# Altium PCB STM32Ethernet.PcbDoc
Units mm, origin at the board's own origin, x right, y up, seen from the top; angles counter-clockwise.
Board outline 35 x 65 mm, 2 copper layers (Top Layer, Bottom Layer), stack 1.646 mm thick; 61 components, 67 nets, 261 pads, 74 vias.
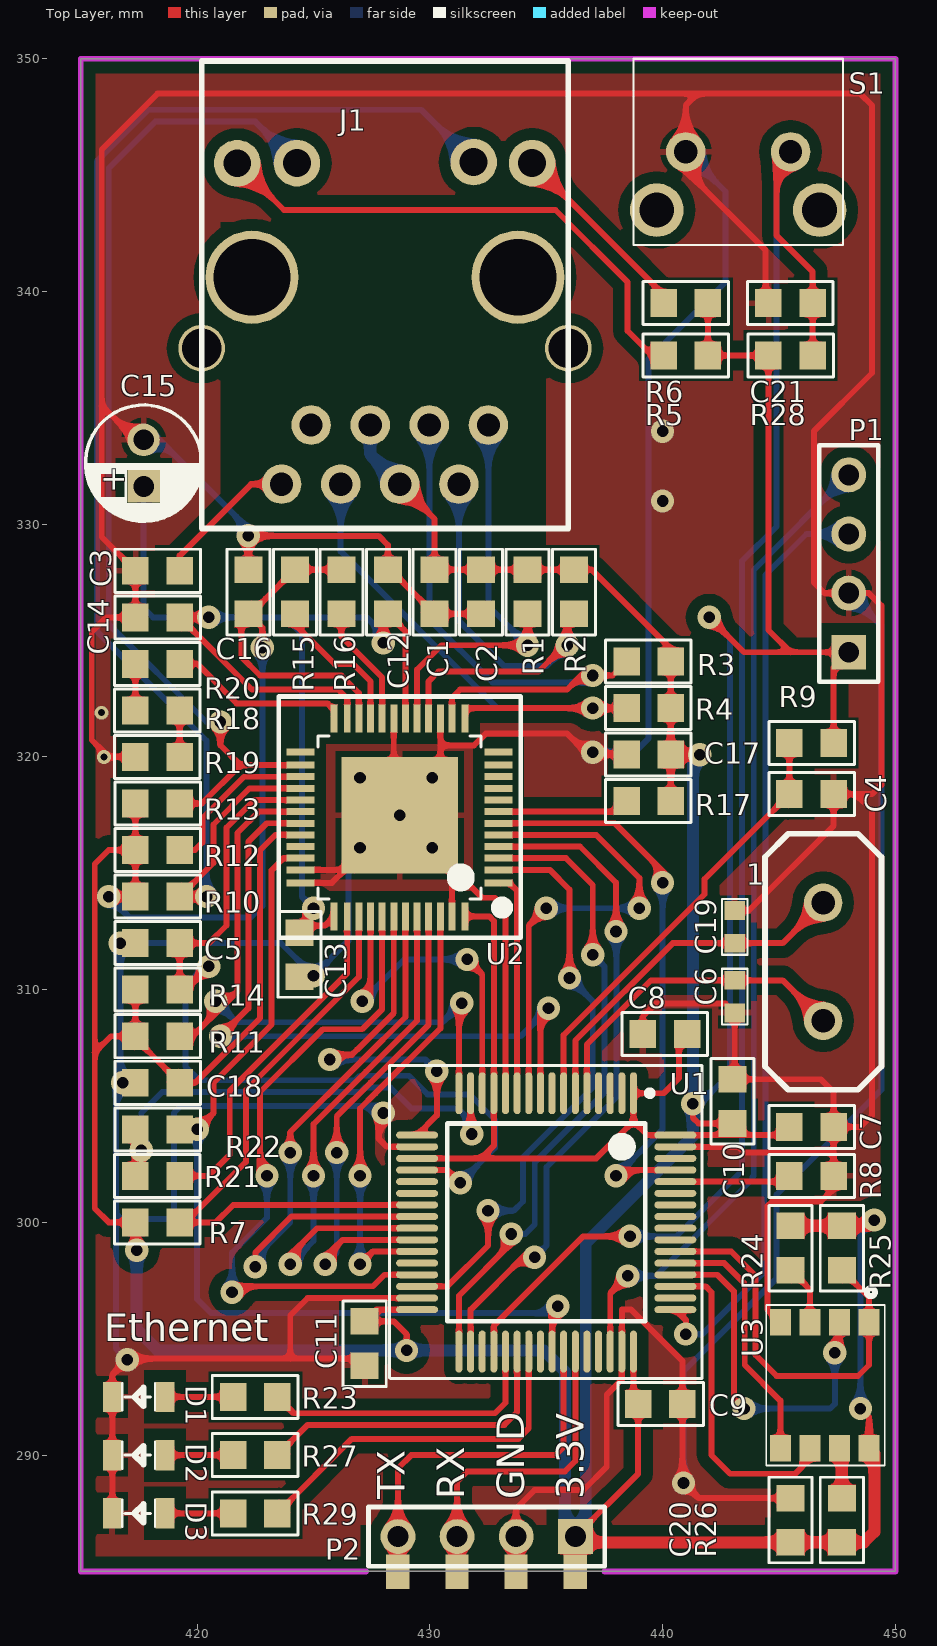
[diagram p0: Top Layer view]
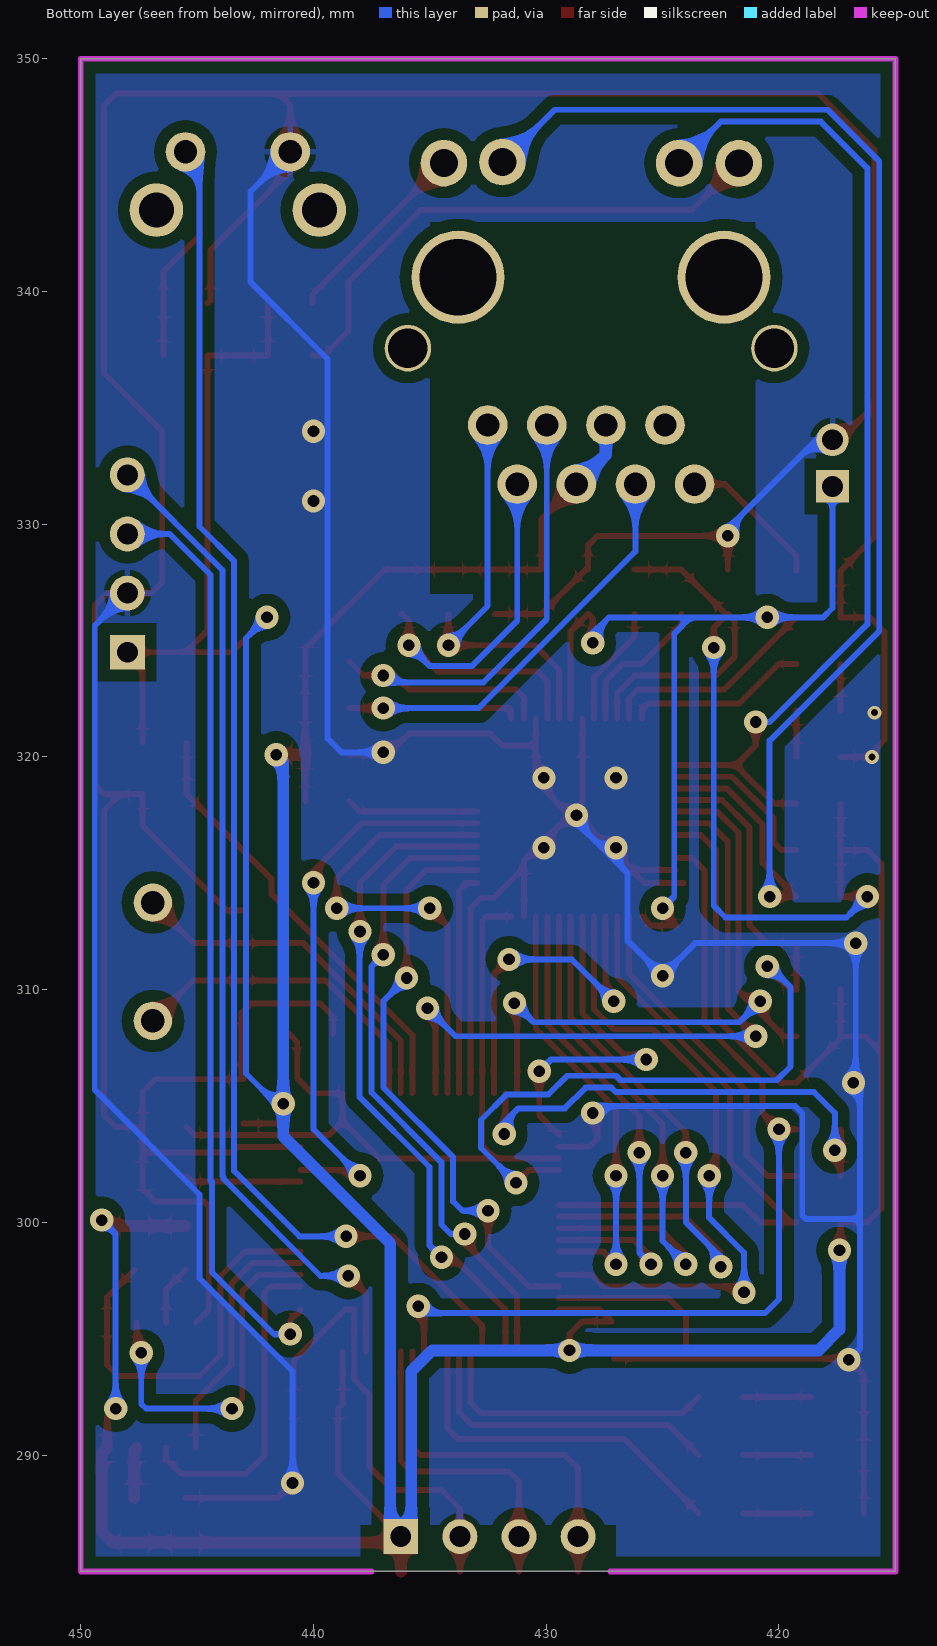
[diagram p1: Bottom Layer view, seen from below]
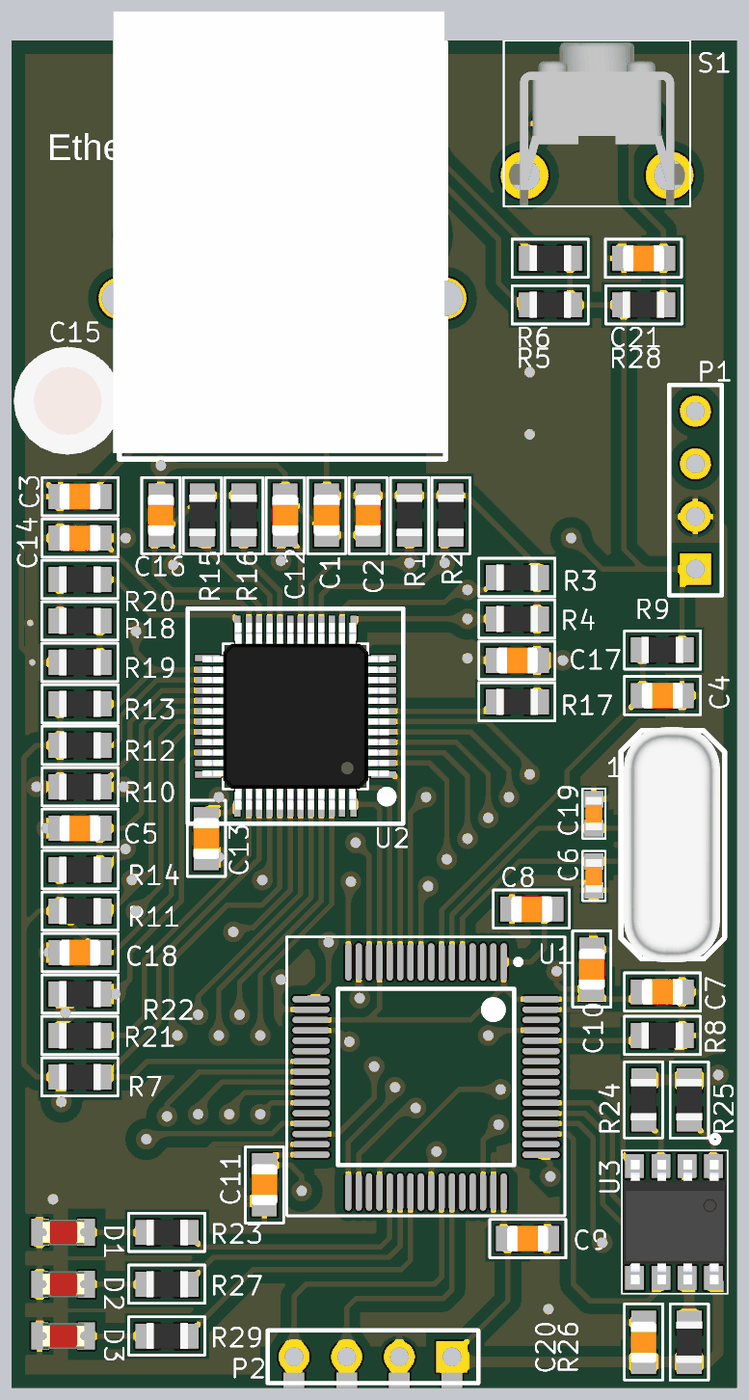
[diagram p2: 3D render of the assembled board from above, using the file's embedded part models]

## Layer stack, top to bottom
Top Solder: solder mask 0.0102, Solder Resist, Dk 3.5
Top Layer: signal copper 0.0356
Dielectric 1: dielectric 1.5748, FR-4, Dk 4.8
Bottom Layer: signal copper 0.0356
Bottom Solder: solder mask 0.0102, Solder Resist, Dk 3.5

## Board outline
415,285 450,285 450,350 415,350

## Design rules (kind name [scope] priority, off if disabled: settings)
Clearance [All] p1: gap=0.508
Length [InNetClass('ETH_SIGN')] p1: maxlimit=45.72 minlimit=43.18
PolygonConnect PAD_GND [(InPadClass('All Pads') AND InNet('GND'))] p1: connectstyle=Relief reliefconductorwidth=0.254 reliefentries=4 polygonreliefangle="90 Angle" airgapwidth=0.254
PolygonConnect [All] p2: connectstyle=Direct reliefconductorwidth=0.254 reliefentries=4 polygonreliefangle="90 Angle" airgapwidth=0.254
RoutingVias [All] p1: holewidth=0.711 width=1.27 viastyle="Through Hole" minholewidth=0.711 minwidth=1.27 maxholewidth=0.711 maxwidth=1.27
SolderMaskExpansion [All] p1: expansion=0.102
Width [All] p1: maxlimit=2.54 minlimit=0.254 preferedwidth=0.254
30 further rules are at their usual default settings.

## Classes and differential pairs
net class ETH_SIGN: ETH_MII_COL ETH_MII_CRS_WKUP ETH_MII_MDC ETH_MII_MDIO ETH_MII_RX_ER ETH_MII_RXD0 ETH_MII_RXD1 ETH_MII_RXD2 ETH_MII_RXD3 ETH_MII_TX_CLK ETH_MII_TX_EN ETH_MII_TXD0 ETH_MII_TXD1 ETH_MII_TXD2 ETH_MII_TXD3 PHY_RESET
net class ETH_CLK: ETH_MCO ETH_MII_RX_CLK PHY_RX_CLK
net class PHY_OUT: RD+ RD- TD+ TD-
net class SPI_DATA: STM_SPI_MISO STM_SPI_MOSI STM_SPI_SCK

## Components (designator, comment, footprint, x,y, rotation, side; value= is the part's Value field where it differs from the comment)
1 "CRY_25MHZ" cry 446.9,311.2 r270 top
C1 "CAP_104_0603" CAP_0805_TOP 430.2,327.1 r270 top
C2 "CAP_104_0603" CAP_0805_TOP 432.2,327.1 r270 top
C3 "CAP_105_0603" CAP_0805_TOP 418.3,328 r0 top
C4 "CAP_102_0603" CAP_0805_TOP 446.4,318.4 r0 top
C5 "CAP_102_0603" CAP_0805_TOP 418.3,312 r0 top
C6 "CAP_18pF_0603" CAP_0603_TOP 443.1,309.7 r270 top
C7 "CAP_104_0603" CAP_0805_TOP 446.4,304.1 r0 top
C8 "CAP_104_0603" CAP_0805_TOP 440.1,308.1 r180 top
C9 "CAP_104_0603" CAP_0805_TOP 439.9,292.2 r0 top
C10 "CAP_104_0603" CAP_0805_TOP 443,305.2 r90 top
C11 "CAP_104_0603" CAP_0805_TOP 427.2,294.8 r270 top
C12 "CAP_104_0603" CAP_0805_TOP 428.2,327.1 r270 top
C13 "CAP_104_0603" CAP_0805_TOP 424.4,311.5 r90 top
C14 "CAP_104_0603" CAP_0805_TOP 418.3,326 r0 top
C15 "CAP_10uF/35V" CAP_10uF/35V 417.7,332.6 r90 top
C16 "CAP_104_0603" CAP_0805_TOP 422.2,327.1 r270 top
C17 "CAP_104_0603" CAP_0805_TOP 439.4,320.1 r180 top
C18 "CAP_104_0603" CAP_0805_TOP 418.3,306 r0 top
C19 "CAP_18pF_0603" CAP_0603_TOP 443.1,312.7 r90 top
C20 "CAP_104_0603" CAP_0805_TOP 445.5,287.2 r90 top
C21 "CAP_102_0603" CAP_0805_TOP 445.5,339.5 r180 top
D1 "LED_RED_0805" "LED 0805 TOP" 417.5,292.5 r0 top
D2 "LED_BLUE_0805" "LED 0805 TOP" 417.5,290 r0 top
D3 "LED_GREEN_0805" "LED 0805 TOP" 417.5,287.5 r0 top
J1 "RJ45" CONNECTOR_RJ45_HR911102A 428.2,340.1 r0 top
P1 "Header 4" HDR1X4 448,324.5 r90 top
P2 "Header 4" HDR1X4 436.25,286.5 r180 top
R1 "Res_49.9R_0805" RES_0805_TOP 434.2,327.1 r270 top
R2 "Res_49.9R_0805" RES_0805_TOP 436.2,327.1 r270 top
R3 "Res_49.9R_0805" RES_0805_TOP 439.4,324.1 r180 top
R4 "Res_49.9R_0805" RES_0805_TOP 439.4,322.1 r180 top
R5 "Res_2.2K_0805" RES_0805_TOP 441,337.25 r180 top
R6 "Res_2.2K_0805" RES_0805_TOP 441,339.5 r180 top
R7 "Res_2.2K_0805" RES_0805_TOP 418.3,300 r180 top
R8 "Res_4.7K_0805" RES_0805_TOP 446.4,302 r0 top
R9 "Res_4.7K_0805" RES_0805_TOP 446.4,320.6 r0 top
R10 "Res_2.2K_0805" RES_0805_TOP 418.3,314 r0 top
R11 "Res_1.5K_0805" RES_0805_TOP 418.3,308 r0 top
R12 "Res_2.2K_0805" RES_0805_TOP 418.3,316 r0 top
R13 "Res_2.2K_0805" RES_0805_TOP 418.3,318 r0 top
R14 "Res_4.7K_0805" RES_0805_TOP 418.3,310 r0 top
R15 "Res_2.2K_0805" RES_0805_TOP 424.2,327.1 r270 top
R16 "Res_2.2K_0805" RES_0805_TOP 426.2,327.1 r270 top
R17 "Res_2.2K_0805" RES_0805_TOP 439.4,318.1 r180 top
R18 "Res_120R_0805" RES_0805_TOP 418.3,322 r180 top
R19 "Res_47R_0805" RES_0805_TOP 418.3,320 r180 top
R20 "Res_4.7K_0805" RES_0805_TOP 418.3,324 r180 top
R21 "Res_0R_0603" RES_0805_TOP 418.3,302 r180 top
R22 "Res_0R_0603" RES_0805_TOP 418.3,304 r0 top
R23 "Res_330R_0805" RES_0805_TOP 422.5,292.5 r180 top
R24 "Res_4.7K_0805" RES_0805_TOP 445.5,298.9 r270 top
R25 "Res_4.7K_0805" RES_0805_TOP 447.7,298.9 r270 top
R26 "Res_4.7K_0805" RES_0805_TOP 447.7,287.2 r90 top
R27 "Res_330R_0805" RES_0805_TOP 422.5,290 r180 top
R28 "Res_4.7K_0805" RES_0805_TOP 445.5,337.25 r0 top
R29 "Res_330R_0805" RES_0805_TOP 422.5,287.5 r180 top
S1 "BUTTON 2P" "Nut nhan 2 chan  dung" 443.5,346 r0 top
U1 "STM32F107" LQFP64_N 435,300 r270 top locked
U2 "DP83848CVV" LQFP48 428.7,317.4 r180 top locked
U3 "S25FL204K" SOIC_8 447,293 r270 top

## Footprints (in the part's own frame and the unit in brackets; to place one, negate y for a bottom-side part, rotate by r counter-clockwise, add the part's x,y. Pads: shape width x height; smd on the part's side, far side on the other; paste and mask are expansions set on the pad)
CAP_10uF/35V [mm]
  rect 1.4x1.4 hole 0.889: 1(-0.975,0)
  round 1.397 hole 0.889: 2(1.025,0)
  silkscreen extent -2.47,-2.5 2.52,2.5, body extent -2.58,-2.57 2.63,2.58, height 0.76
CAP_0603_TOP [mm]
  rect 0.8x0.9 smd: 1(-0.7,0) 2(0.7,0)
  silkscreen extent -1.2,-0.55 1.2,0.55, body extent -0.8,-0.4 0.8,0.4, height 0.7
CAP_0805_TOP [mm]
  rect 1.14x1.2 smd: 1(-0.95,0) 2(0.95,0)
  silkscreen extent -1.83,-0.92 1.85,0.93, body extent -1,-0.62 1,0.63, height 0.8
CONNECTOR_RJ45_HR911102A [mm] "Single Port RJ45 Connector with Integrated Magnetics and LED"
  round 1.7 hole 1: 1(4.317,-5.837) 2(3.047,-8.377) 3(1.777,-5.837) 4(0.507,-8.377) 5(-0.763,-5.837) 6(-2.033,-8.377) 7(-3.303,-5.837) 8(-4.573,-8.377)
  round 2 hole 1.2: 9(6.197,5.413) 10(3.683,5.461) 11(-3.913,5.413) 12(-6.477,5.41)
  round 2 hole 1.7: ""(-8.003,-2.537) ""(7.747,-2.537)
  round 4 hole 3.3: ""(-5.843,0.513) ""(5.587,0.513)
  silkscreen extent -8,-10.29 7.75,9.8, body extent -8.3,-10 7.7,11.3, height 13.42
cry [mil]
  round 65 hole 40: 1(-100,0) 2(100,0)
  silkscreen extent -217,-98 217,98, body extent -223,-93 223,90, height 146
HDR1X4 [mm] "Connector; Header; 4 Position"
  rect 1.5x1.5 hole 0.9: 1(0,0)
  round 1.5 hole 0.9: 2(2.54,0) 3(5.08,0) 4(7.62,0)
  silkscreen extent -1.27,-1.27 8.89,1.27
"LED 0805 TOP" [mm]
  rect 0.8x1.3 smd: 1(1.118,0) 2(-1.143,0)
  silkscreen extent -0.71,-0.58 0.69,0.58, body extent -1.01,-0.62 1.01,0.63, height 1.1
LQFP48 [mm] "Thin QFP, 48-Leads, Body 7x7mm, Pitch 0.5mm, IPC Medium Density"
  rect 1.2x0.3 smd paste+0 mask+0.07: 1(-4.25,2.81) 2(-4.25,2.25) 3(-4.25,1.75) 4(-4.25,1.25) 5(-4.25,0.75) 6(-4.25,0.25) 7(-4.25,-0.25) 8(-4.25,-0.75) 9(-4.25,-1.25) 10(-4.25,-1.75) 11(-4.25,-2.25) 12(-4.25,-2.81) 25(4.25,-2.81) 26(4.25,-2.25) 27(4.25,-1.75) 28(4.25,-1.25) 29(4.25,-0.75) 30(4.25,-0.25) 31(4.25,0.25) 32(4.25,0.75) 33(4.25,1.25) 34(4.25,1.75) 35(4.25,2.25) 36(4.25,2.81)
  rect 0.3x1.2 smd paste+0 mask+0.07: 13(-2.81,-4.25) 14(-2.25,-4.25) 15(-1.75,-4.25) 16(-1.25,-4.25) 17(-0.75,-4.25) 18(-0.25,-4.25) 19(0.25,-4.25) 20(0.75,-4.25) 21(1.25,-4.25) 22(1.75,-4.25) 23(2.25,-4.25) 24(2.81,-4.25) 37(2.81,4.25) 38(2.25,4.25) 39(1.75,4.25) 40(1.25,4.25) 41(0.75,4.25) 42(0.25,4.25) 43(-0.25,4.25) 44(-0.75,4.25) 45(-1.25,4.25) 46(-1.75,4.25) 47(-2.25,4.25) 48(-2.81,4.25)
  silkscreen extent -5.2,-5.2 5.2,5.18, body extent -4.5,-4.5 4.5,4.5, height 1.5
LQFP64_N [mm] "Thin QFP, 64-Leads, Body 10x10mm, Pitch 0.5mm, IPC Medium Density"
  oval 1.8x0.3 smd: 1(-5.55,3.75) 2(-5.55,3.25) 3(-5.55,2.75) 4(-5.55,2.25) 5(-5.55,1.75) 6(-5.55,1.25) 7(-5.55,0.75) 8(-5.55,0.25) 9(-5.55,-0.25) 10(-5.55,-0.75) 11(-5.55,-1.25) 12(-5.55,-1.75) 13(-5.55,-2.25) 14(-5.55,-2.75) 15(-5.55,-3.25) 16(-5.55,-3.75) 33(5.55,-3.75) 34(5.55,-3.25) 35(5.55,-2.75) 36(5.55,-2.25) 37(5.55,-1.75) 38(5.55,-1.25) 39(5.55,-0.75) 40(5.55,-0.25) 41(5.55,0.25) 42(5.55,0.75) 43(5.55,1.25) 44(5.55,1.75) 45(5.55,2.25) 46(5.55,2.75) 47(5.55,3.25) 48(5.55,3.75)
  oval 0.3x1.8 smd: 17(-3.75,-5.55) 18(-3.25,-5.55) 19(-2.75,-5.55) 20(-2.25,-5.55) 21(-1.75,-5.55) 22(-1.25,-5.55) 23(-0.75,-5.55) 24(-0.25,-5.55) 25(0.25,-5.55) 26(0.75,-5.55) 27(1.25,-5.55) 28(1.75,-5.55) 29(2.25,-5.55) 30(2.75,-5.55) 31(3.25,-5.55) 32(3.75,-5.55) 49(3.75,5.55) 50(3.25,5.55) 51(2.75,5.55) 52(2.25,5.55) 53(1.75,5.55) 54(1.25,5.55) 55(0.75,5.55) 56(0.25,5.55) 57(-0.25,5.55) 58(-0.75,5.55) 59(-1.25,5.55) 60(-1.75,5.55) 61(-2.25,5.55) 62(-2.75,5.55) 63(-3.25,5.55) 64(-3.75,5.55)
  silkscreen extent -5.67,-4.25 4.25,4.58, body extent -5,-5 5,5, height 1.6
"Nut nhan 2 chan  dung" [mm]
  round 1.7 hole 1: 1(2,0) 2(-2.5,0)
  round 2.3 hole 1.5: 3(-3.75,-2.5) 4(3.25,-2.5)
  silkscreen extent -4.75,-4 4.25,4, body extent -4.55,-3.95 4.05,3.9, height 7.8
RES_0805_TOP [mm]
  rect 1.14x1.2 smd: 1(-0.95,0) 2(0.95,0)
  silkscreen extent -1.83,-0.92 1.85,0.93, body extent -1,-0.62 1,0.62, height 0.5
SOIC_8 [mm]
  rect 1.14x0.91 smd: 1(-2.7,1.87) 2(-2.7,0.6) 3(-2.7,-0.67) 4(-2.7,-1.94) 5(2.7,-1.94) 6(2.7,-0.67) 7(2.7,0.6) 8(2.7,1.87)
  silkscreen extent -4.17,-2.55 3.45,2.55, body extent -3,-2.5 3.01,2.5, height 1.75

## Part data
1: library part cry, "Crystal Oscillator"
C1 C2 C3 C4 C5 C6 C7 C8 C9 C10 C11 C12 C13 C14 C16 C17 C18 C19 C20 C21: library part "Cap 1206 BUT", "Capacitor"
C15: library part "CAP P"
D1 D2 D3: library part "LED 0805 TOP", "Typical INFRARED GaAs LED"
J1: "RJ45 Connector, with Leds"
P1 P2: "Header, 4-Pin"
R1 R2 R3 R4 R5 R6 R7 R8 R9 R10 R11 R12 R13 R14 R15 R16 R17 R18 R19 R20 R21 R22 R23 R24 R25 R26 R27 R28 R29: library part Res, "Resistor"
S1: "Switch"
U1: library part STM32F103RBT6, "STM32 ARM-based 32-bit MCU with 128 Kbytes Flash, 64-pin LQFP, Industrial Temperature"

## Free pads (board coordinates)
  rect 1x1.5 smd: 0(428.625,284.988) 0(431.165,284.988) 0(433.705,284.988) 0(436.245,284.988)
  rect 5x5 smd: 0(428.7,317.5)

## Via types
v1: diameter 1, hole 0.5, Top Layer to Bottom Layer, tented both sides, 72 vias
v2: diameter 0.6, hole 0.3, Top Layer to Bottom Layer, tented both sides, 2 vias

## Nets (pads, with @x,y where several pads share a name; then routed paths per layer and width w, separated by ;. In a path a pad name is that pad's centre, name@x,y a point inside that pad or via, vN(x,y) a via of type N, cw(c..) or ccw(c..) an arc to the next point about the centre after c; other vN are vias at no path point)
3.3V: C1.1 C2.1 C7.1 C8.1 C9.1 C10.1 C11.1 C16.2 C17.1 C18.2 C20.1 J1.4 J1.5 P1.1 P2.1 pad.0@436.245,284.988 R1.1 R2.1 R3.1 R4.1 R5.1 R6.1 R7.2 R9.2 R10.1 R11.1 R12.1 R13.1 R14.1 R15.1 R16.1 R17.1 R24.1 R25.1 R26.1 R28.1 U1.1 U1.13 U1.19 U1.32 U1.48 U1.64 U2.22 U2.32 U2.48 U3.8 | length 305.9
  Top Layer w0.254: v1(416.2,314) R10.1 R12.1 ; R14.1 R11.1 ; R13.1 R12.1 ; v1(417.4,298.8) 417.35,298.85 R7.2 416.2,300 415.6,300.6 415.6,307.3 ; v1(422.8,324.7) 422.8,325.55 C16.2 ; U2.32 423.36,316.65 422.7,315.99 422.7,308.775 419.925,306 C18.2 417.35,307.9 R11.1 ; R16.1 R15.1 422.3,326.15 C16.2 ; U2.22 426.95,322.75 426.2,323.5 422.7,323.5 421.9,324.3 421.9,325.85 C16.2 ; J1.4 430.2,330.23 C1.1 C2.1 R1.1 R2.1 436.95,328.05 440.35,324.65 R3.1 R4.1 C17.1 R17.1 ; v1(429,294.5) 429,295.2 428.45,295.75 C11.1 427.7,296.25 U1.32 ; U1.19 432.2,302.75 ; U2.48 432.55,313.15 432.75,312.95 U1.13 432.75,303.3 432.2,302.75 ; P2.1@436.245,286.495 P2.1 438.95,289.2 438.95,292 438.75,292.2 U1.48 ; C8.1 440.7,307.75 440.7,306.2 440.05,305.55 U1.1 438.75,304.35 ; v1(441.3,305.1) 441.3,304.5 441.55,304.25 C10.1 ; R6.1 R5.1 R28.1 444.55,325.45 445.5,324.5 ; v1(442,326) 443.5,324.5 445.5,324.5 ; C7.1 445.1,303.75 U1.64 439.35,303.75 438.75,304.35 ; R9.2 447.35,323.85 P1.1 445.5,324.5 ; v1(448.5,292) 448.87,291.63 U3.8 ; 415.6,307.3 416.3,308 R11.1 ; 415.6,307.3 415.6,315.4 416.2,316 R12.1 ; 432.2,302.75 437.15,302.75 438.75,304.35
  Top Layer w0.508: pad.0@436.245,284.988 436.245,286.495 436.49,286.25 C20.1 R26.1 448.65,286.25 449.1,286.7 449.1,290.07 U3.8 ; C17.1 v1(441.6,320.1) ; R24.1 R25.1 448.85,299.85 v1(449.1,300.1)
  Bottom Layer w0.254: v1(416.2,314) 417.1,313.1 422.3,313.1 422.8,313.6 v1(422.8,324.7) ; v1(441.3,305.1) 441.6,305.1 442.9,306.4 442.9,325.1 v1(442,326) ; v1(448.5,292) 448.5,299.5 v1(449.1,300.1)
  Bottom Layer w0.508: v1(417.4,298.8) 417.4,295.4 418.3,294.5 v1(429,294.5) 434.9,294.5 435.8,293.6 435.8,286.95 P2.1 436.7,286.95 436.7,299.1 441.3,303.7 v1(441.3,305.1) 441.3,319.8 v1(441.6,320.1) ; J1.5 427.437,332.993 J1.4
ESP_RESET: U1.21
ETH_MCO: R22.2 U1.41 U2.34 | length 39.9
  Top Layer w0.254: R22.2 v1(420,304) 420.7,304.7 420.7,306 423.2,308.5 423.2,315.13 423.507,315.437 423.507,315.442 423.715,315.65 U2.34 ; U1.41 435.25,296.15 v1(435.5,296.4)
  Bottom Layer w0.254: v1(420,304) 420,296.7 420.6,296.1 435.2,296.1 v1(435.5,296.4)
ETH_MII_COL: U1.17 U2.42 | length 15.7
  Top Layer w0.254: v1@425.6,307.2 426.65,307.2 426.872,307.423 426.879,307.423 428.45,308.993 U2.42 ; U1.17 430.3,304.6 v1(430.3,306.5)
  Bottom Layer w0.254: v1(425.7,307) 429.8,307 v1(430.3,306.5)
ETH_MII_CRS_WKUP: U1.14 U2.40 | length 15.1
  Top Layer w0.254: v1(427.1,309.5) 427.45,309.85 U2.40 ; v1(431.6,311.3) 432.25,310.65 U1.14
  Bottom Layer w0.254: v1(427.1,309.5) 428.9,311.3 v1(431.6,311.3)
ETH_MII_MDC: U1.9 U2.31 | length 30.1
  Top Layer w0.254: v1(421,308) 422.2,309.2 422.2,316.36 422.99,317.15 U2.31 ; U1.9 434.75,308.85 v1@435.2,309.3
  Bottom Layer w0.254: v1(421,308) 433.9,308 v1@435.2,309.3
  other v1: 435.1,309.2
ETH_MII_MDIO: R11.2 U1.16 U2.30 | length 28.4
  Top Layer w0.254: R11.2 419.8,308 421.73,309.93 421.73,316.73 422.65,317.65 U2.30 ; U1.16 431.25,309.305 v1(431.368,309.423)
  Bottom Layer w0.254: v1(420.8,309.5) 421.7,308.6 430.545,308.6 v1(431.368,309.423)
ETH_MII_PPS_OUT: U1.57
ETH_MII_RX_CLK: R21.2 R22.1 U1.15 | length 20.7
  Top Layer w0.254: R21.2 R22.1 ; v1@431.75,304.25 U1.15
  Bottom Layer w0.254: v1(417.6,303.1) 417.6,304.7 418.5,305.6 427.01,305.6 427.202,305.792 428.308,305.792 429.2,304.9 431.2,304.9 431.8,304.3 v1(431.8,303.8)
ETH_MII_RX_DV: R7.1 U1.23 U2.39 | length 27
  Top Layer w0.254: U2.39 426.95,310.542 422.1,305.692 422.1,302.6 419.5,300 R7.1 420.8,300 421.55,300.75 U1.23
ETH_MII_RX_ER: U1.29 U2.41 | length 28.4
  Top Layer w0.254: v1(421.5,297) 421.5,297.1 421.657,297.257 427.557,297.257 428.05,297.75 U1.29 ; v1(423,302) 422.7,302.3 422.7,305.6 425.4,308.3 427.092,308.3 427.95,309.158 U2.41
  Bottom Layer w0.254: v1(421.5,297) 421.5,298.7 423,300.2 v1(423,302)
ETH_MII_RXD0: U1.24 U2.43 | length 25.9
  Top Layer w0.254: v1(422.5,298.1) 422.5,298.7 424.05,300.25 U1.24 ; v1(424,303) 424,303.886 427.067,306.953 427.074,306.953 428.95,308.829 U2.43
  Bottom Layer w0.254: v1(422.5,298.1) 422.5,298.5 424,300 v1(424,303)
ETH_MII_RXD1: U1.25 U2.44 | length 23.5
  Top Layer w0.254: v1(424,298.2) 424,298.6 425.15,299.75 U1.25 ; v1(425,302) 425,304.221 427.262,306.483 427.268,306.483 429.45,308.664 U2.44
  Bottom Layer w0.254: v1(424,298.2) 425,299.2 v1(425,302)
ETH_MII_RXD2: U1.26 U2.45 | length 21.4
  Top Layer w0.254: v1(425.5,298.2) 425.5,298.5 426.25,299.25 U1.26 ; v1(426,303) 426,304.557 427.456,306.013 427.463,306.013 429.95,308.5 U2.45
  Bottom Layer w0.254: v1(425.5,298.2) 426,298.7 v1(426,303)
ETH_MII_RXD3: U1.27 U2.46 | length 19.1
  Top Layer w0.254: v1(427,298.2) 427.55,298.75 U1.27 ; v1(427,302) 427,304.892 427.651,305.543 427.658,305.543 430.45,308.335 U2.46
  Bottom Layer w0.254: v1(427,298.2) v1(427,302)
ETH_MII_TX_CLK: U1.11 U2.1 | length 9.6
  Top Layer w0.254: U2.1 433.41,314.59 433.75,314.25 U1.11
ETH_MII_TX_EN: U1.30 U2.2 | length 25.4
  Top Layer w0.254: U1.30 430.75,297.25 432.5,299 v1(432.5,300.5) ; U2.2 435.15,315.15 436,314.3 v1(436,310.5)
  Bottom Layer w0.254: v1(432.5,300.5) 433.6,300.5 434,300.9 434,302.8 437,305.8 437,309.5 v1(436,310.5)
ETH_MII_TXD0: U1.33 U2.3 | length 27.7
  Top Layer w0.254: U1.33 431.25,296.85 433.5,299.1 v1(433.5,299.5) ; U2.3 435.85,315.65 437,314.5 v1(437,311.5)
  Bottom Layer w0.254: v1(433.5,299.5) 434.1,299.5 434.508,299.908 434.508,302.59 437.508,305.59 437.508,310.992 v1(437,311.5)
ETH_MII_TXD1: U1.34 U2.4 | length 28.7
  Top Layer w0.254: U1.34 431.75,296.25 434,298.5 v1(434.5,298.5) ; U2.4 436.45,316.15 438,314.6 v1(438,312.5)
  Bottom Layer w0.254: v1(434.5,298.5) 435.016,299.016 435.016,302.379 438.016,305.379 438.016,312.484 v1(438,312.5)
ETH_MII_TXD2: U1.10 U2.5 | length 20.4
  Top Layer w0.254: U2.5 437.15,316.65 439,314.8 v1(439,313.5) ; U1.10 434.25,312.75 v1(435,313.5)
  Bottom Layer w0.254: v1(435,313.5) 435.6,313.5 v1(439,313.5)
ETH_MII_TXD3: U1.61 U2.6 | length 24.5
  Top Layer w0.254: U2.6 437.95,317.15 439.45,315.65 440,315.1 v1(440,314.6) ; v1(438,302) 438.25,302.25 U1.61
  Bottom Layer w0.254: v1(438,302) 440,304 v1(440,314.6)
GND: C1.2 C2.2 C3.1 C4.2 C5.1 C6.2 C7.2 C8.2 C9.2 C10.2 C11.2 C12.1 C13.1 C14.1 C15.2 C16.1 C17.2 C18.1 C19.2 C20.2 C21.2 D1.2 D2.2 D3.2 P1.2 P2.2 pad.0@428.7,317.5 pad.0@433.705,284.988 R8.2 R19.2 S1.2 U1.12 U1.18 U1.31 U1.47 U1.63 U2.15 U2.19 U2.35 U2.36 U2.47 U3.4 | length 408.2
  Top Layer w0.254: D3.2 D2.2 D1.2 416.357,293.457 417.05,294.15 424,294.15 ; R19.2 416.2,320 415.47,320.73 415.47,325.37 416.1,326 C14.1 C3.1 415.9,329.45 415.9,335.1 ; C15.2 417.375,333.625 415.9,335.1 ; C16.1 v1(422.2,329.5) 427.8,329.5 428.2,329.1 C12.1 428.3,328.05 C1.2 C2.2 ; U2.36@424.09,314.59 U2.36 425.79,314.59 pad.0@426.35,315.15 ; U2.35 pad.0@426.35,315.15 ; C11.2@427.1,294.15 424,294.15 ; v1(428,304.7) 427.8,304.5 427.8,303.6 428.15,303.25 U1.18 ; U2.19 428.45,318.05 pad.0@429,317.5 ; U1.31 424.75,296.75 424,296 424,294.15 ; U2.15 430.45,320.5 ; U2.47 430.95,315.55 pad.0@429,317.5 ; pad.0@430.95,315.25 432.25,313.95 432.8,313.95 433.25,313.5 U1.12 ; pad.0@433.705,284.988 433.705,287.705 434.5,288.5 436.6,288.5 437.6,289.5 437.6,292.6 438.25,293.25 U1.47 438.25,296.25 438.65,296.25 440.85,294.05 440.85,288.85 v1(440.9,288.8) 441.55,288.15 C20.2 ; C17.2 436.8,320.1 435.9,321 432.4,321 431.9,320.5 430.45,320.5 ; C8.2 439.15,308.85 439.7,309.4 442.7,309.4 C6.2 443.1,306.25 C10.2 446.8,306.15 447.35,305.6 C7.2 ; U1.63 440.557,303.243 443.257,303.243 443.5,303 447.35,303 ; C19.2 443.7,313.4 447.35,317.05 C4.2 448.3,318.4 ; C21.2 444.43,339.62 444.43,341.77 441,345.2 S1.2 441,348 441.5,348.5 ; U3.4 444.5,296.26 444.5,300.7 444.7,300.9 446.8,300.9 447.35,301.45 R8.2 447.35,303 ; 415.9,335.1 415.9,346.1 418.3,348.5 441.5,348.5 ; pad.0@426.35,315.15 v1(428.7,317.5) pad.0@429,317.5 ; pad.0@429,317.5 430.45,318.95 430.45,320.5 ; 441.5,348.5 448.5,348.5 449,348 449,336.5 446.5,334 446.5,327.5 446.96,327.04 P1.2 448.86,327.04 449.4,326.5 449.4,318.8 449,318.4 448.3,318.4 ; 447.35,303 C7.2 ; C7.2 448.5,304.1 449,304.6 449,317.7 448.3,318.4
  Bottom Layer w0.254: v1(417,294.1) 416.519,294.581 416.519,300.15 ; C15.2 418.375,333.625 422.2,329.8 v1(422.2,329.5) ; v1(428,304.7) 427.7,305 419.3,305 419,304.7 419,300.3 418.85,300.15 416.519,300.15 ; v1(428.7,317.5) 428.7,317.2 426.5,315 426.5,312.1 v1(425,310.6) 423.6,312 v1(416.7,312) 416.7,306.1 v1(416.8,306) 416.519,305.719 416.519,300.15 ; v1(437,320.2) 438.8,320.2 439.4,320.8 439.4,337.1 442.7,340.4 442.7,344.3 S1.2 ; v1(440.9,288.8) 440.9,293.6 444.9,297.6 444.9,301.2 449.4,305.7 449.4,325.64 P1.2
  other v1: 427,316.1 430.1,316.1 427,319.1 430.1,319.1 440,331 440,334
  other v2: 416,320 415.9,321.9
NetC3_2: C3.2 J1.8 | length 6.3
  Top Layer w0.254: C3.2 419.25,328.65 422.323,331.723 J1.8
NetC4_1: C4.1 R9.1 U1.7 | length 19.1
  Top Layer w0.254: U1.7 435.75,308.05 441.8,314.1 441.8,314.75 C4.1 R9.1
NetC12_2: C12.2 C13.2 C14.2 C15.1 U2.18 U2.23 U2.37 | length 48.9
  Top Layer w0.254: v1(420.5,326) C14.2 422.35,322.9 426.065,322.9 426.45,322.515 U2.23 ; v1(425,313.5) 425,313.35 424.4,312.75 425.49,312.75 U2.37 ; v1(428,324.9) 428,325.95 C12.2 428.95,325.4 U2.18
  Bottom Layer w0.254: C15.1 417.7,326.4 418.1,326 v1(420.5,326) 423.8,326 ; v1(425,313.5) 424.5,314 424.5,325.3 423.8,326 ; v1(428,324.9) 428,325.3 427.3,326 423.8,326
NetD1_1: D1.1 R23.2 | length 2.9
  Top Layer w0.254: D1.1 R23.2
NetD2_1: D2.1 R27.2 | length 2.9
  Top Layer w0.254: D2.1 R27.2
NetD3_1: D3.1 R29.2 | length 2.9
  Top Layer w0.254: D3.1 R29.2
NetJ1_9: J1.9 R6.2 | length 8.4
  Top Layer w0.254: J1.9 440.05,339.86 R6.2
NetJ1_12: J1.12 R5.2 | length 23
  Top Layer w0.254: J1.12 423.733,343.5 435.4,343.5 438.5,340.4 438.5,338.3 439.55,337.25 R5.2
NetR8_1: R8.1 U1.60 | length 5
  Top Layer w0.254: U1.60 445.2,301.75 R8.1
NetR12_2: R12.2 U2.27 | length 7.1
  Top Layer w0.254: R12.2 419.9,316 420.23,316.33 420.23,317.366 422.015,319.15 U2.27
NetR15_2: R15.2 U2.21 | length 6.3
  Top Layer w0.254: R15.2 424.2,325.7 425.9,324 426.7,324 427.45,323.25 U2.21
NetR16_2: R16.2 U2.20 | length 5.2
  Top Layer w0.254: R16.2 426.2,325.165 427.95,323.415 U2.20
NetR17_2: R17.2 U2.7 | length 5.7
  Top Layer w0.254: U2.7 438,317.65 R17.2
NetR18_1: R18.1 R19.1 | length 2
  Top Layer w0.254: R19.1 R18.1
NetR18_2: R18.2 R20.2 | length 2
  Top Layer w0.254: R18.2 R20.2
NetR20_1: R20.1 U2.24 | length 7.8
  Top Layer w0.254: R20.1 420,324 421.7,322.3 425.6,322.3 425.89,322.01 U2.24
NetR24_2: R24.2 U3.3 | length 2.6
  Top Layer w0.254: R24.2 446.33,297.12 U3.3
NetR26_2: R26.2 U3.7 | length 2.2
  Top Layer w0.508: U3.7 447.7,290.2 R26.2
OSC_IN: 1.2 C6.1 U1.5 | length 14.1
  Top Layer w0.254: U1.5 436.75,307.65 439.5,310.4 C6.1 445.16,310.4 1.2
OSC_OUT: 1.1 C19.1 U1.6 | length 15.4
  Top Layer w0.254: U1.6 436.25,307.815 440.435,312 C19.1 445.16,312 1.1
PA6: U1.22
PC0: U1.8
PHY_LED_ACT: J1.11 R13.2 U2.26 | length 43.9
  Top Layer w0.254: R13.2 420.2,318 421.85,319.65 ; v1(421,321.5) 421,320.5 421.85,319.65 ; U2.26 421.85,319.65
  Bottom Layer w0.254: v1(421,321.5) 420.4,321.5 416.2,325.7 416.2,345.3 418.2,347.3 422.5,347.3 J1.11
PHY_LED_LINK: J1.10 R10.2 U2.28 | length 60.8
  Top Layer w0.254: v1(420.4,314) R10.2 420.7,315.45 420.7,317.1 422.25,318.65 U2.28
  Bottom Layer w0.254: v1(420.4,314) 420.4,320.7 415.692,325.408 415.692,345.592 417.908,347.808 429.636,347.808 J1.10
PHY_RESET: C5.2 R14.2 U1.20 U2.29 | length 38.5
  Top Layer w0.254: v1(420.5,311) 419.5,310 R14.2 C5.2 420.5,312 421.26,312.76 421.26,316.96 422.45,318.15 U2.29 ; U1.20 430.75,302.25 v1(431.3,301.7)
  Bottom Layer w0.254: v1(420.5,311) 420.4,311 419.5,310.1 419.5,306.7 420.092,306.108 426.8,306.108 426.992,306.3 429.1,306.3 429.9,305.5 431.7,305.5 432.8,304.4 432.8,303.2 v1(431.3,301.7)
PHY_RX_CLK: R21.1 U2.38 | length 14.9
  Top Layer w0.254: R21.1 420.5,302 421.4,302.9 421.4,305.657 426.45,310.707 U2.38
RD+: J1.3 R3.2 U2.14 | length 25.7
  Top Layer w0.254: U2.14 430.95,322.55 431.3,322.9 435.9,322.9 436.5,323.5 v1(437,323.5) 437.85,323.5 R3.2
  Bottom Layer w0.254: J1.3 429.977,325.923 432.7,323.2 436.7,323.2 v1(437,323.5)
RD-: J1.6 R4.2 U2.13 | length 23.8
  Top Layer w0.254: U2.13 431.51,322.01 431.6,322.1 v1(437,322.1) R4.2
  Bottom Layer w0.254: J1.6 426.167,328.833 432.9,322.1 v1(437,322.1)
STM_BUTTON: C21.1 R28.2 S1.1 U1.36 | length 68.8
  Top Layer w0.254: U1.36 432.75,295.558 436.592,299.4 v1(438.6,299.4) ; S1.1 444.9,345.4 444.9,342.4 446.45,340.85 C21.1 R28.2
  Bottom Layer w0.254: v1(438.6,299.4) 440.6,299.4 443.408,302.208 443.408,328.408 444.9,329.9 444.9,345.4 S1.1
STM_I2C1_SCL: U1.58
STM_I2C1_SDA: U1.59
STM_LED1: R23.1 U1.37 | length 12.5
  Top Layer w0.254: R23.1 424.15,291.8 432.8,291.8 433.25,292.25 U1.37
STM_LED2: R27.1 U1.38 | length 13.7
  Top Layer w0.254: R27.1 424.75,291.3 433.2,291.3 433.75,291.85 U1.38
STM_LED3: R29.1 U1.39 | length 15.6
  Top Layer w0.254: R29.1 426.65,290.7 433.8,290.7 434.25,291.15 U1.39
STM_LED4: U1.40
STM_SPI_CS: R25.2 U1.54 U3.1 | length 17.3
  Top Layer w0.254: U1.54 442.95,298.75 444,297.7 444,294.3 444.9,293.4 448.4,293.4 448.87,293.87 U3.1 448.87,296.78 R25.2
STM_SPI_MISO: U1.52 U3.2 | length 15.6
  Top Layer w0.254: U1.52 442.35,297.75 443.06,297.04 443.06,292.44 v1(443.5,292) ; v1(447.4,294.4) 447.6,294.6 U3.2
  Bottom Layer w0.254: v1(443.5,292) 447.2,292 447.4,292.2 v1(447.4,294.4)
STM_SPI_MOSI: U1.53 U3.5 | length 11
  Top Layer w0.254: U1.53 442.65,298.25 443.53,297.37 443.53,293.87 445.06,292.34 U3.5
STM_SPI_SCK: U1.51 U3.6 | length 13.9
  Top Layer w0.254: U1.51 441.85,297.25 442.1,297 442.1,290 442.9,289.2 445.7,289.2 446.33,289.83 U3.6
STM_USART1_RX: P2.3 pad.0@431.165,284.988 U1.43 | length 14
  Top Layer w0.254: pad.0@431.165,284.988 431.165,286.495 P2.3 431.17,288.87 431.6,289.3 435.8,289.3 436.25,289.75 U1.43
STM_USART1_TX: P2.4 pad.0@428.625,284.988 U1.42 | length 16
  Top Layer w0.254: pad.0@428.625,284.988 428.625,286.495 P2.4 428.63,289.43 429.2,290 435.4,290 435.75,290.35 U1.42
SWCLK: P1.3 U1.49 | length 40
  Top Layer w0.254: U1.49 441,295.8 v1(441,295.2)
  Bottom Layer w0.254: v1(441,295.2) 441.7,295.2 444.37,297.87 444.37,301.733 444.424,301.787 444.424,327.824 446.18,329.58 P1.3
SWDIO: P1.4 U1.46 | length 42.6
  Top Layer w0.254: U1.46 437.75,296.95 v1(438.5,297.7)
  Bottom Layer w0.254: v1(438.5,297.7) 439.7,297.7 443.862,301.862 443.862,301.943 443.916,301.998 443.916,328.036 P1.4
TD+: J1.1 R1.2 U2.17 | length 18.8
  Top Layer w0.254: U2.17 429.45,323.75 430.5,324.8 v1(434.2,324.8) R1.2
  Bottom Layer w0.254: J1.1 432.517,326.483 v1(434.2,324.8)
TD-: J1.2 R2.2 U2.16 | length 21.4
  Top Layer w0.254: U2.16 429.95,323.25 430.37,323.67 434.67,323.67 435.8,324.8 v1(435.9,324.8) 435.9,325.85 R2.2
  Bottom Layer w0.254: J1.2 431.247,325.853 433.2,323.9 435,323.9 v1(435.9,324.8)
pads on no net: J1. J1.7 S1.3 S1.4 U1.2 U1.3 U1.4 U1.28 U1.35 U1.44 U1.45 U1.50 U1.55 U1.56 U1.62 U2.8 U2.9 U2.10 U2.11 U2.12 U2.25 U2.33

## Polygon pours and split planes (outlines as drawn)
GND on Top Layer "Bottom Layer-No Net" (solid, remove dead copper, pour order 7): 415,350 450,350 450,285 438,285 438,287 427,287 427,285 415,285
GND on Bottom Layer "Bottom Layer-No Net" (solid, remove dead copper, pour order 6): 415,350 450,350 450,285 438,285 438,287 427,287 427,285 415,285

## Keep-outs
Keep-Out Layer:
  lines w0.254: 437.5,285 450,285 450,350 415,350 ; 415,350 415,285 427.25,285 ; 415,350 415,350 ; 427.25,285 427.25,285

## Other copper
Multi-Layer:
  pour cut-out: 421,343 435,343 435,327 421,327

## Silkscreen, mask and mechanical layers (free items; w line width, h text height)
Top Overlay:
  lines w0.127: 428.275,293.325 428.3,293.3 441.7,293.3 441.7,306.75 428.275,306.75 428.275,293.325
  text "Ethernet" at 416,294.5 h2.03
  text "TX" at 429.3,288.1 h2.03 r90
  text "RX" at 431.865,288.1 h2.03 r90
  text "GND" at 434.451,288.1 h2.03 r90
  text "3.3V" at 437,288.1 h2.03 r90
